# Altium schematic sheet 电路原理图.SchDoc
size A4
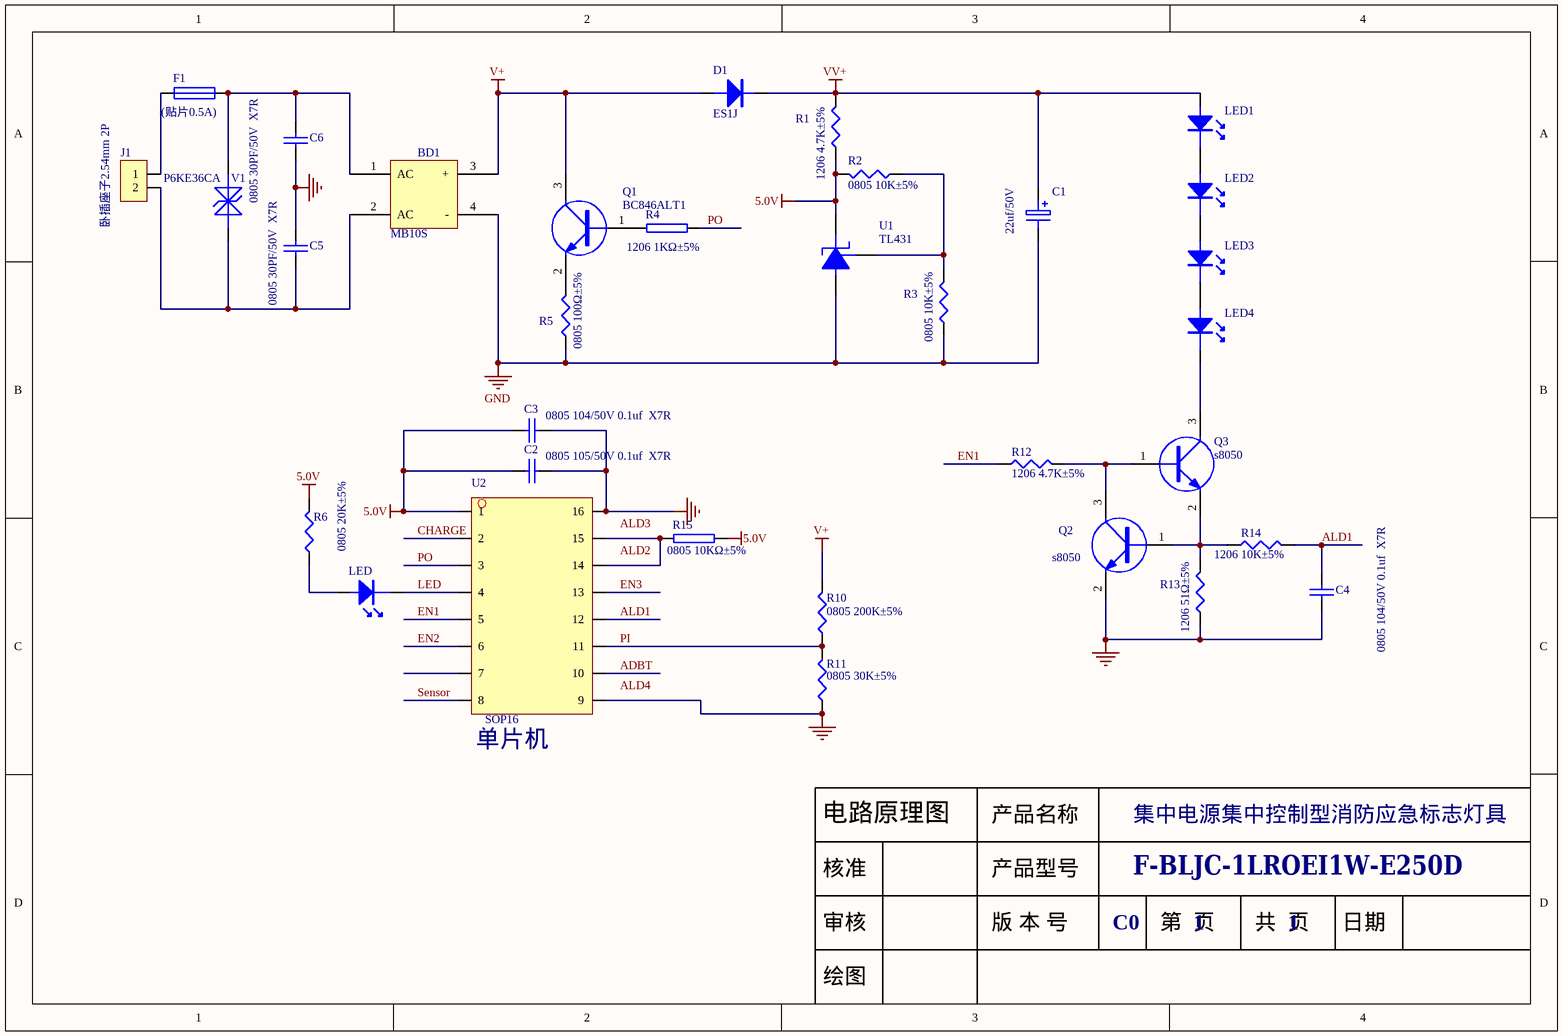
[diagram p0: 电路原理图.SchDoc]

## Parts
BD1  MB10S  [BM6S]
C1  22uf/50V  [CES6.3]
C2  0805 105/50V 0.1uf  X7R  [0805-C]
C3  0805 104/50V 0.1uf  X7R  [0805-C]
C4  0805 104/50V 0.1uf  X7R  [0805-C]
C5  0805 30PF/50V  X7R  [0805-C]
C6  0805 30PF/50V  X7R  [0805-C]
D1  ES1J  [sma]
F1  (贴片0.5A)  [1206]
J1  卧插座子2.54mm 2P  [XH-2.5-2PTW]
LED  (no value)  [LED0805]
LED1  (no value)  [LED2_l]
LED2  (no value)  [LED2_l]
LED3  (no value)  [LED2_l]
LED4  (no value)  [LED2_l]
Q1  BC846ALT1  [SOT-23]
Q2  s8050  [SOT-23]
Q3  s8050  [SOT-23]
R1  1206 4.7K±5%  [1206]
R2  0805 10K±5%  [0805]
R3  0805 10K±5%  [0805]
R4  1206 1KΩ±5%  [1206]
R5  0805 100Ω±5%  [0805]
R6  0805 20K±5%  [0805]
R10  0805 200K±5%  [0805]
R11  0805 30K±5%  [0805]
R12  1206 4.7K±5%  [1206]
R13  1206 51Ω±5%  [1206]
R14  1206 10K±5%  [1206]
R15  0805 10KΩ±5%  [0805]
U1  TL431  [SOT23-A2]
U2  SOP16  [SOP-16b]
V1  P6KE36CA  [SMT_TVS]

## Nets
5.0V: C2.2 C3.2 R1.1 R2.2 R6.2 R15.1 U1.2 U2.1
GND: BD1.4(-) C1.2 C2.1 C3.1 C4.1 C5.1 C6.2 Q2.2(E) R3.1 R5.1 R11.1 R13.1 U1.3 U2.9 U2.16
V+: BD1.3(+) D1.A Q1.3(C) R10.2
VV+: C1.1 D1.K LED1.A R1.2
ADBT: U2.10
ALD1: C4.2 R14.2 U2.12
CHARGE: U2.2
EN1: R12.1 U2.5
EN2: U2.6
EN3: U2.13
LED: LED.K U2.4
PI: R10.1 R11.2 U2.11
PO: R4.2 U2.3
Sensor: U2.8
NetBD1_1: BD1.1(AC) C6.1 F1.2 V1.A
NetBD1_2: BD1.2(AC) C5.2 J1.2 V1.K
NetF1_1: F1.1 J1.1
NetLED1_K: LED1.K LED2.A
NetLED2_K: LED2.K LED3.A
NetLED3_K: LED3.K LED4.A
NetLED4_K: LED4.K Q3.3(C)
NetLED_A: LED.A R6.1
NetQ1_1: Q1.1(B) R4.1
NetQ1_2: Q1.2(E) R5.2
NetQ2_1: Q2.1(B) Q3.2(E) R13.2 R14.1
NetQ2_3: Q2.3(C) Q3.1(B) R12.2
NetR2_1: R2.1 R3.2 U1.1
NetR15_2: R15.2 U2.14 U2.15

Not connected (* = marked no-connect by the designer): U2 7

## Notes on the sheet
- (near U2) 单片机
- 集中电源集中控制型消防应急标志灯具
- F-BLJC-1LROEⅠ1W-E250D
- C0
- 1
- Labels drawn without touching a wire or pin: ALD2, ALD3, ALD4

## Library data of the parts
BD1 = BRIDGE2: 料号: 4.3.X.042; 型号规格: MB10S SOP-4-0.5A-1000V; 名称: 贴片桥堆
C1 = ELECTRO1: 料号: 4.1.C.151; 型号规格: 150uF/50V ±20% 6000H φ8*16mm-40~105℃ 脚长L=8.5±0.5mm RoHS; 名称: 电解电容
C2-C4 = CAP: 料号: 4.1.CTX.004; 型号规格: 104/50V ±10% X7R; 名称: 0603封装贴片电容
C5 C6 = CAP: 料号: 4.1.CTX.054; 型号规格: 30pF/50V ±10% X7R 5000H; 名称: 0603封装贴片电容
D1 = DIODE: 料号: 4.3.D.033; 型号规格: ES1D 1A/200V  SMA -55~125℃ RoHS，编带; 名称: 贴片超快恢复二极管
F1 = FUSE1: 料号: 4.3.X.111; 型号规格: 24F系列 快断保险管 2A250V; 名称: 贴片保险管
J1 = CON2: 型号规格: XH2.5-2A白色卧式针座; 名称: 直插针座
LED LED1-LED4 = LED: 料号: 4.3.LED.250; 名称: 发光二极管; 型号规格: C0805UG-ES 高亮白发绿贴片 VF:2.8-3.0 IV:250-300 WLD:515-520  IF:30MA
Q1-Q3 = NPN
R1-R3 R6 R10-R14 = RES1: 料号: 4.2.RTD.246; 型号规格: 15R(15Ω) ±1%RoHS; 名称: 0805封装贴片电阻
R4 R15 = RES2: 料号: 4.2.RTX.002; 型号规格: 102(1KΩ) ±5%; 名称: 0603封装贴片电阻
R5 = RES1: 料号: 4.2.RTD.244; 型号规格: 680(68Ω) ±5%; 名称: 0805封装贴片电阻
V1 = TVS1: 料号: 4.3.DT.064; 型号规格: 瞬态二极管 P6KE43CA SMT_TVS; 名称: 贴片瞬态二极管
